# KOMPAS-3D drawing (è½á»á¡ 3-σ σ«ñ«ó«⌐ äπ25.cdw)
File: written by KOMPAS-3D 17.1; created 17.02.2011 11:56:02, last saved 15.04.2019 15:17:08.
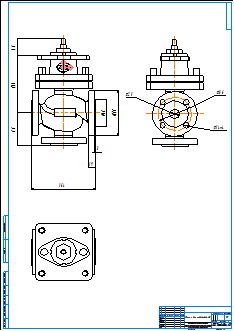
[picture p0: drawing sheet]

Title block, sheet 1: name: Клапан 3-х ходовой Ду25; material: Внимание! Данный продукт является объектом авторского права ООО «Торговый Дом АДЛ». / Запрещается изменение, копирование, распространение / (в том числе путем копирования на другие сайты и ресурсы в Интернете) / или любое иное использование информации и объектов без предварительного / согласия правообладателя (ООО «Торговый Дом АДЛ»).; scale: 1:1; sheets: 1; organisation: ООО "Торговый дом АДЛ"; sheet format: A1; stored path: \\adlc.lan\data\АДЛ_ПКД\3D-модели\ADL production\Клапаны ГРАНРЕГ\Трёхходовой клапан КМ307Ф\KOMPAS 2D\Клапан 3-х ходовой Ду25.cdw

Views: Спереди 1, Проекционный вид 2, Проекционный вид 3
Dimensions and other numbers on the sheet: 146; 82; 43; 164; 3; 19; 68; 115; 25; 86; 14; 1:1; 1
